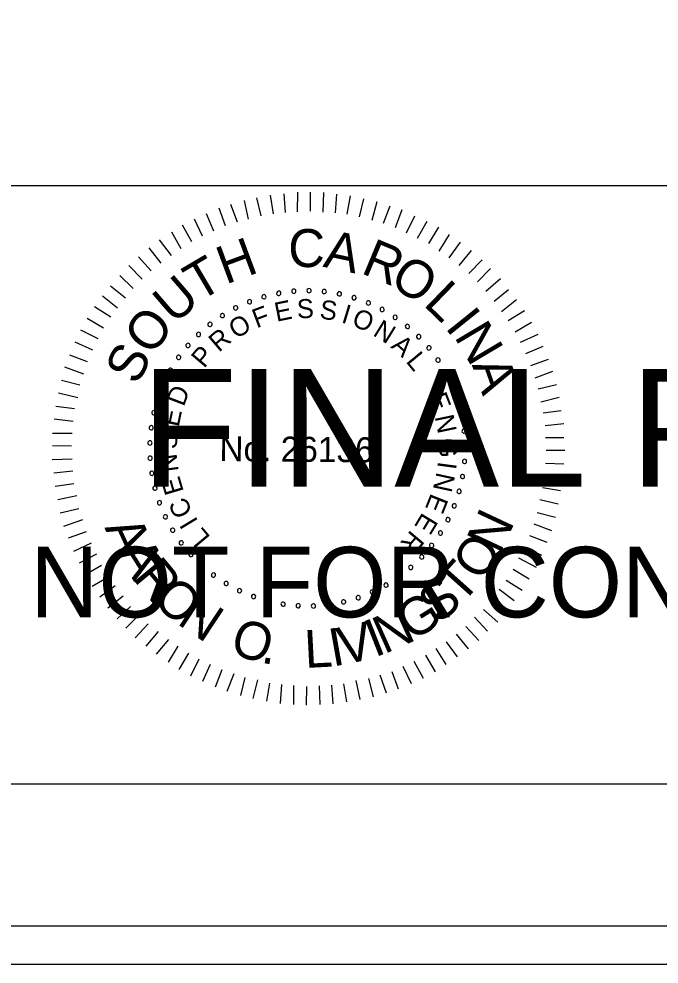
# Model space of a CAD drawing. Extents: x 967 to 1326, y 964 to 2584.
# Drawn here: x 1170.56 to 1189.3, y 963.72 to 991.36 of the extents above; entities that cross this region are included whole.
import ezdxf

# ---------------------------------------------------------------- set-up
doc = ezdxf.new("R2010")
doc.units = 0
for name, color, linetype in [('RD_SHT_Misc1', 7, 'Continuous'), ('RD_SHT_Misc2', 7, 'Continuous'), ('RD_XS_ExPaveRet', 7, 'Continuous'), ('RD_XS_TX_Elev_EX', 7, 'Continuous')]:
    doc.layers.add(name, color=color, linetype=linetype)

msp = doc.modelspace()

# ---------------------------------------------------------------- linework, layer by layer
at = {"layer": 'RD_SHT_Misc1'}
for p, q in [((1178.01, 985.663), (1177.93, 986.209)), ((1178.364, 985.699), (1178.33, 986.244)), ((1178.717, 985.719), (1178.722, 986.295)), ((1179.093, 985.739), (1179.098, 986.292)), ((1179.469, 985.713), (1179.489, 986.288)), ((1179.829, 985.687), (1179.872, 986.231)), ((1180.174, 985.646), (1180.271, 986.19)), ((1176.964, 985.419), (1176.769, 985.935)), ((1177.287, 985.508), (1177.169, 986.054)), ((1177.657, 985.597), (1177.53, 986.128)), ((1180.535, 985.573), (1180.662, 986.102)), ((1180.902, 985.478), (1181.045, 986.022)), ((1176.264, 985.156), (1176.053, 985.657)), ((1176.61, 985.306), (1176.423, 985.83)), ((1181.231, 985.384), (1181.428, 985.896)), ((1181.584, 985.265), (1181.78, 985.786)), ((1175.933, 985.005), (1175.699, 985.506)), ((1181.905, 985.109), (1182.154, 985.606)), ((1182.226, 984.953), (1182.506, 985.45)), ((1175.308, 984.634), (1175.036, 985.12)), ((1175.624, 984.846), (1175.352, 985.332)), ((1182.562, 984.789), (1182.85, 985.27)), ((1175.03, 984.445), (1174.681, 984.9)), ((1182.86, 984.572), (1183.163, 985.053)), ((1183.158, 984.378), (1183.484, 984.828)), ((1174.729, 984.217), (1174.372, 984.665)), ((1183.447, 984.145), (1183.811, 984.587)), ((1174.435, 983.997), (1174.062, 984.399)), ((1183.729, 983.92), (1184.116, 984.316)), ((1174.172, 983.753), (1173.776, 984.148)), ((1183.98, 983.672), (1184.368, 984.061)), ((1173.909, 983.479), (1173.52, 983.858)), ((1184.232, 983.394), (1184.657, 983.767)), ((1173.684, 983.197), (1173.242, 983.546)), ((1184.475, 983.108), (1184.892, 983.45)), ((1173.451, 982.9), (1173.009, 983.256)), ((1184.687, 982.807), (1185.128, 983.156)), ((1173.257, 982.64), (1172.776, 982.936)), ((1173.039, 982.312), (1172.559, 982.6)), ((1184.885, 982.544), (1185.355, 982.832)), ((1185.081, 982.213), (1185.56, 982.493)), ((1172.883, 982.006), (1172.379, 982.256)), ((1185.24, 981.904), (1185.756, 982.145)), ((1172.727, 981.677), (1172.215, 981.904)), ((1185.399, 981.573), (1185.907, 981.791)), ((1172.571, 981.333), (1172.051, 981.53)), ((1185.549, 981.226), (1186.057, 981.414)), ((1172.461, 980.974), (1171.91, 981.178)), ((1185.669, 980.865), (1186.185, 981.06)), ((1172.351, 980.652), (1171.807, 980.787)), ((1185.759, 980.541), (1186.297, 980.667)), ((1172.286, 980.276), (1171.727, 980.419)), ((1185.832, 980.165), (1186.371, 980.298)), ((1172.191, 979.955), (1171.647, 980.029)), ((1185.906, 979.842), (1186.436, 979.906)), ((1172.15, 979.587), (1171.598, 979.653)), ((1185.964, 979.473), (1186.51, 979.53)), ((1172.124, 979.234), (1171.548, 979.239)), ((1185.977, 979.12), (1186.514, 979.115)), ((1172.105, 978.866), (1171.545, 978.871)), ((1185.997, 978.751), (1186.542, 978.747)), ((1172.118, 978.482), (1171.542, 978.471)), ((1185.971, 978.368), (1186.508, 978.348)), ((1172.138, 978.136), (1171.585, 978.072)), ((1185.952, 978.022), (1186.497, 977.949)), ((1172.173, 977.768), (1171.627, 977.688)), ((1185.888, 977.655), (1186.417, 977.566)), ((1172.262, 977.414), (1171.701, 977.296)), ((1185.808, 977.302), (1186.345, 977.175)), ((1172.321, 977.037), (1171.774, 976.911)), ((1185.729, 976.926), (1186.265, 976.792)), ((1172.425, 976.707), (1171.871, 976.519)), ((1185.634, 976.597), (1186.146, 976.401)), ((1172.53, 976.36), (1172.007, 976.173)), ((1185.508, 976.253), (1186.013, 976.057)), ((1172.681, 976.029), (1172.165, 975.788)), ((1172.831, 975.705), (1172.323, 975.441)), ((1185.352, 975.924), (1185.857, 975.675)), ((1185.188, 975.603), (1185.7, 975.33)), ((1172.982, 975.374), (1172.497, 975.094)), ((1185.024, 975.274), (1185.498, 974.987)), ((1173.194, 975.042), (1172.709, 974.762)), ((1184.822, 974.946), (1185.288, 974.658)), ((1173.384, 974.78), (1172.936, 974.453)), ((1184.62, 974.687), (1185.055, 974.353)), ((1173.612, 974.478), (1173.164, 974.129)), ((1184.403, 974.389), (1184.814, 974.033)), ((1173.832, 974.177), (1173.437, 973.812)), ((1184.155, 974.092), (1184.574, 973.72)), ((1174.091, 973.945), (1173.689, 973.541)), ((1183.899, 973.864), (1184.28, 973.454)), ((1174.35, 973.674), (1173.97, 973.263)), ((1183.644, 973.597), (1184.024, 973.18)), ((1174.64, 973.442), (1174.275, 973.022)), ((1174.937, 973.209), (1174.58, 972.782)), ((1183.358, 973.37), (1183.715, 972.944)), ((1175.212, 973.014), (1174.932, 972.549)), ((1182.764, 972.952), (1183.059, 972.482)), ((1183.065, 973.141), (1183.384, 972.709)), ((1175.525, 972.812), (1175.245, 972.331)), ((1182.463, 972.755), (1182.743, 972.269)), ((1175.83, 972.633), (1175.588, 972.136)), ((1176.159, 972.477), (1175.94, 971.98)), ((1181.8, 972.431), (1182.041, 971.93)), ((1182.124, 972.581), (1182.396, 972.08)), ((1176.503, 972.321), (1176.307, 971.816)), ((1176.855, 972.211), (1176.651, 971.69)), ((1177.177, 972.1), (1177.05, 971.572)), ((1181.122, 972.175), (1181.31, 971.652)), ((1181.476, 972.28), (1181.664, 971.771)), ((1177.545, 972.036), (1177.409, 971.484)), ((1177.897, 971.933), (1177.808, 971.412)), ((1178.25, 971.892), (1178.207, 971.34)), ((1178.603, 971.866), (1178.598, 971.313)), ((1178.978, 971.84), (1178.974, 971.295)), ((1179.355, 971.86), (1179.365, 971.307)), ((1179.715, 971.88), (1179.749, 971.327)), ((1180.061, 971.915), (1180.149, 971.393)), ((1180.423, 972.012), (1180.541, 971.458)), ((1180.791, 972.07), (1180.926, 971.54))]:
    msp.add_line(p, q, dxfattribs=at)
for centre, start, end in [((1178.609, 983.397), 5.0653, 185.0653), ((1179.055, 983.414), 359.5268, 179.5268), ((1179.5, 983.388), 353.9884, 173.9884), ((1177.312, 983.091), 21.6807, 201.6807), ((1177.734, 983.235), 16.1422, 196.1422), ((1177.734, 983.235), 196.1422, 16.1422), ((1178.168, 983.337), 10.6038, 190.6038), ((1178.168, 983.337), 190.6038, 10.6038), ((1178.609, 983.397), 185.0653, 5.0653), ((1179.055, 983.414), 179.5268, 359.5268), ((1179.5, 983.388), 173.9884, 353.9884), ((1179.94, 983.319), 168.4499, 348.4499), ((1179.94, 983.319), 348.4499, 168.4499), ((1180.372, 983.208), 162.9114, 342.9114), ((1180.372, 983.208), 342.9114, 162.9114), ((1176.906, 982.908), 27.2191, 207.2191), ((1176.906, 982.908), 207.2191, 27.2191), ((1177.312, 983.091), 201.6807, 21.6807), ((1180.79, 983.056), 157.373, 337.373), ((1180.79, 983.056), 337.373, 157.373), ((1181.193, 982.864), 151.8345, 331.8345), ((1181.193, 982.864), 331.8345, 151.8345), ((1176.52, 982.686), 32.7576, 212.7576), ((1176.52, 982.686), 212.7576, 32.7576), ((1181.574, 982.634), 146.2961, 326.2961), ((1181.574, 982.634), 326.2961, 146.2961), ((1176.156, 982.428), 38.2961, 218.2961), ((1176.156, 982.428), 218.2961, 38.2961), ((1181.932, 982.368), 140.7576, 320.7576), ((1181.932, 982.368), 320.7576, 140.7576), ((1175.82, 982.135), 43.8345, 223.8345), ((1175.82, 982.135), 223.8345, 43.8345), ((1182.263, 982.069), 135.2191, 315.2191), ((1182.263, 982.069), 315.2191, 135.2191), ((1175.513, 981.812), 49.373, 229.373), ((1175.513, 981.812), 229.373, 49.373), ((1182.563, 981.74), 129.6807, 309.6807), ((1182.563, 981.74), 309.6807, 129.6807), ((1175.239, 981.461), 54.9114, 234.9114), ((1175.239, 981.461), 234.9114, 54.9114), ((1182.83, 981.383), 124.1422, 304.1422), ((1182.83, 981.383), 304.1422, 124.1422), ((1175, 981.085), 60.4499, 240.4499), ((1175, 981.085), 240.4499, 60.4499), ((1183.061, 981.002), 118.6038, 298.6038), ((1183.061, 981.002), 298.6038, 118.6038), ((1174.798, 980.687), 65.9884, 245.9884), ((1174.798, 980.687), 245.9884, 65.9884), ((1183.255, 980.601), 293.0653, 113.0653), ((1183.255, 980.601), 113.0653, 293.0653), ((1174.636, 980.272), 71.5268, 251.5268), ((1174.636, 980.272), 251.5268, 71.5268), ((1183.408, 980.182), 107.5268, 287.5268), ((1183.408, 980.182), 287.5268, 107.5268), ((1174.514, 979.843), 77.0653, 257.0653), ((1174.514, 979.843), 257.0653, 77.0653), ((1183.521, 979.751), 101.9884, 281.9884), ((1183.521, 979.751), 281.9884, 101.9884), ((1174.435, 979.405), 82.6038, 262.6038), ((1174.435, 979.405), 262.6038, 82.6038), ((1183.592, 979.311), 96.4499, 276.4499), ((1183.592, 979.311), 276.4499, 96.4499), ((1174.398, 978.961), 88.1422, 268.1422), ((1174.398, 978.961), 268.1422, 88.1422), ((1183.619, 978.866), 90.9114, 270.9114), ((1183.619, 978.866), 270.9114, 90.9114), ((1174.404, 978.515), 93.6807, 273.6807), ((1174.404, 978.515), 273.6807, 93.6807), ((1183.604, 978.421), 85.373, 265.373), ((1183.604, 978.421), 265.373, 85.373), ((1174.453, 978.072), 99.2191, 279.2191), ((1174.453, 978.072), 279.2191, 99.2191), ((1183.546, 977.979), 79.8345, 259.8345), ((1183.546, 977.979), 259.8345, 79.8345), ((1174.545, 977.636), 104.7576, 284.7576), ((1174.545, 977.636), 284.7576, 104.7576), ((1183.445, 977.545), 74.2961, 254.2961), ((1183.445, 977.545), 254.2961, 74.2961), ((1174.678, 977.211), 110.2961, 290.2961), ((1174.678, 977.211), 290.2961, 110.2961), ((1183.303, 977.122), 68.7576, 248.7576), ((1183.303, 977.122), 248.7576, 68.7576), ((1174.852, 976.8), 115.8345, 295.8345), ((1174.852, 976.8), 295.8345, 115.8345), ((1183.121, 976.716), 63.2191, 243.2191), ((1183.121, 976.716), 243.2191, 63.2191), ((1175.065, 976.409), 121.373, 301.373), ((1175.065, 976.409), 301.373, 121.373), ((1182.9, 976.328), 57.6807, 237.6807), ((1182.9, 976.328), 237.6807, 57.6807), ((1175.314, 976.039), 126.9114, 306.9114), ((1175.314, 976.039), 306.9114, 126.9114), ((1182.643, 975.964), 52.1422, 232.1422), ((1182.643, 975.964), 232.1422, 52.1422), ((1175.598, 975.696), 132.4499, 312.4499), ((1175.598, 975.696), 312.4499, 132.4499), ((1182.353, 975.627), 46.6038, 226.6038), ((1175.914, 975.381), 137.9884, 317.9884), ((1175.914, 975.381), 317.9884, 137.9884), ((1182.353, 975.627), 226.6038, 46.6038), ((1176.258, 975.099), 143.5268, 323.5268), ((1176.258, 975.099), 323.5268, 143.5268), ((1182.03, 975.319), 41.0653, 221.0653), ((1182.03, 975.319), 221.0653, 41.0653), ((1176.629, 974.851), 149.0653, 329.0653), ((1176.629, 974.851), 329.0653, 149.0653), ((1181.305, 974.803), 29.9884, 209.9884), ((1181.68, 975.043), 35.5268, 215.5268), ((1181.68, 975.043), 215.5268, 35.5268), ((1177.021, 974.639), 154.6038, 334.6038), ((1177.021, 974.639), 334.6038, 154.6038), ((1180.908, 974.6), 24.4499, 204.4499), ((1180.908, 974.6), 204.4499, 24.4499), ((1181.305, 974.803), 209.9884, 29.9884), ((1177.432, 974.467), 160.1422, 340.1422), ((1177.432, 974.467), 340.1422, 160.1422), ((1177.858, 974.335), 165.6807, 345.6807), ((1177.858, 974.335), 345.6807, 165.6807), ((1178.294, 974.245), 351.2191, 171.2191), ((1180.065, 974.313), 13.373, 193.373), ((1180.065, 974.313), 193.373, 13.373), ((1180.494, 974.436), 18.9114, 198.9114), ((1180.494, 974.436), 198.9114, 18.9114), ((1178.294, 974.245), 171.2191, 351.2191), ((1178.737, 974.198), 356.7576, 176.7576), ((1178.737, 974.198), 176.7576, 356.7576), ((1179.183, 974.193), 2.2961, 182.2961), ((1179.183, 974.193), 182.2961, 2.2961), ((1179.627, 974.232), 7.8345, 187.8345), ((1179.627, 974.232), 187.8345, 7.8345)]:
    msp.add_arc(centre, 0.0627, start, end, dxfattribs=at)
at = {"layer": 'RD_XS_ExPaveRet'}
for points in [[(967.409, 963.72), (1326.285, 963.72), (1326.285, 1183.72), (967.409, 1183.72)], [(988.525, 964.84), (1326.285, 964.84), (1326.285, 1182.6), (988.525, 1182.6)]]:
    msp.add_lwpolyline(points, close=True, dxfattribs=at)
at = {"layer": 'RD_XS_TX_Elev_EX'}
for p, q in [((996.114, 986.486), (1323.886, 986.486)), ((1323.886, 968.983), (996.114, 968.983))]:
    msp.add_line(p, q, dxfattribs=at)

# ---------------------------------------------------------------- texts
at = {"layer": 'RD_SHT_Misc1'}
for s, height, rotation, p in [('C', 1.11, 359.5482, (1178.442, 984.108)), ('A', 1.11, 348.1981, (1179.439, 984.115)), ('H', 1.11, 20.3637, (1176.614, 983.587)), ('R', 1.11, 337.4344, (1180.541, 983.937)), ('T', 1.11, 30.4992, (1175.828, 983.072)), ('O', 1.108, 326.5869, (1181.366, 983.609)), ('U', 1.11, 40.8022, (1175.102, 982.403)), ('L', 1.11, 315.9488, (1182.373, 983.003)), ('S', 0.557, 2.208, (1178.709, 982.601)), ('F', 0.557, 20.6127, (1177.52, 982.309)), ('E', 0.557, 11.4103, (1178.103, 982.503)), ('S', 0.557, 352.6608, (1179.346, 982.599)), ('I', 0.557, 343.1136, (1179.975, 982.491)), ('I', 1.11, 308.6613, (1183.011, 982.338)), ('O', 1.11, 52.0267, (1174.435, 981.474)), ('O', 0.557, 30.8477, (1176.917, 981.987)), ('O', 0.557, 338.4392, (1180.274, 982.401)), ('N', 0.557, 328.2042, (1180.896, 982.12)), ('N', 1.11, 300.7037, (1183.285, 982.075)), ('R', 0.557, 40.3949, (1176.415, 981.594)), ('A', 0.557, 318.657, (1181.424, 981.762)), ('S', 1.108, 63.2511, (1174.029, 980.619)), ('P', 0.557, 49.9421, (1175.985, 981.124)), ('L', 0.557, 309.4546, (1181.869, 981.339)), ('A', 1.11, 289.4792, (1183.814, 981.243)), ('D', 0.557, 69.0364, (1175.386, 980.003)), ('E', 0.557, 291.049, (1182.53, 980.307)), ('E', 0.557, 78.2388, (1175.238, 979.407)), ('N', 0.557, 281.8466, (1182.728, 979.726)), ('S', 0.557, 87.786, (1175.187, 978.772)), ('No. 26136', 0.7311, 359.5268, (1176.429, 978.43)), ('G', 0.557, 272.2995, (1182.833, 979.097)), ('N', 0.557, 97.3332, (1175.242, 978.137)), ('I', 0.557, 262.4084, (1182.83, 978.437)), ('E', 0.557, 106.5355, (1175.394, 977.541)), ('N', 0.557, 257.7339, (1182.789, 978.127)), ('E', 0.557, 248.1867, (1182.628, 977.511)), ('C', 0.557, 116.4266, (1175.661, 976.938)), ('E', 0.557, 238.9844, (1182.378, 976.949)), ('N', 1.105, 64.8922, (1184.632, 975.684)), ('A', 1.105, 294.7297, (1173.062, 976.486)), ('I', 0.557, 121.1011, (1175.823, 976.67)), ('L', 0.557, 129.9595, (1176.187, 976.204)), ('R', 0.557, 229.782, (1182.041, 976.435)), ('O', 1.105, 56.2059, (1184.102, 974.874)), ('A', 1.105, 302.2892, (1173.414, 975.72)), ('R', 1.105, 309.8487, (1173.865, 975.007)), ('T', 1.105, 48.2685, (1183.515, 974.211)), ('O', 1.105, 317.7861, (1174.434, 974.33)), ('S', 1.105, 40.3311, (1182.842, 973.636)), ('N', 1.105, 326.4725, (1175.158, 973.686)), ('G', 1.105, 32.0198, (1182.059, 973.14)), ('N', 1.105, 24.0824, (1181.252, 972.776)), ('O', 1.105, 342.3472, (1176.697, 972.82)), ('V', 1.105, 12.7741, (1180.033, 972.457)), ('I', 1.105, 21.4605, (1180.976, 972.681)), ('L', 1.105, 2.9677, (1178.943, 972.379)), ('I', 1.105, 10.1523, (1179.743, 972.418)), ('.', 1.105, 351.0336, (1177.623, 972.536))]:
    msp.add_text(s, height=height, rotation=rotation, dxfattribs=at).set_placement(p)
at = {"layer": 'RD_SHT_Misc2'}
for s, height, p in [('FINAL PLANS', 3.4375, (1174.145, 977.685)), ('NOT FOR CONSTRUCTION', 2.0625, (1170.901, 973.86))]:
    msp.add_text(s, height=height, dxfattribs=at).set_placement(p)

doc.saveas('drawing.dxf')
